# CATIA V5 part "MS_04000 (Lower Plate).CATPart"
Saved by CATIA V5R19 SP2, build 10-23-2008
Part number: MS_04000 (Lower Plate)
Bounding box of the stored display mesh (mm): x -1462.666 to 0, y -324.52 to 322.101, z 0 to 422.967
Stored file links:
  D:\EPSA\GIT\ELIZ-2022\01 - Maquette CATIA\MS_Miscellanous_Finish_Assembly\MS_A0400 (Firewall)\MS_04000 (Lower Plate).CATPart
  D:\EPSA\GIT\ELIZ-2022\01 - Maquette CATIA\MS_Miscellanous_Finish_Assembly\MS_A0400 (Firewall)\MS_A0400 (FireWall).CATProduct
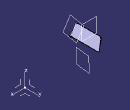
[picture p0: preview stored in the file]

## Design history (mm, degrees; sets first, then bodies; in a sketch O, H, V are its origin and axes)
AxisSystem1: origin (0, 0, 0), X (1, 0, 0), Y (0, 1, 0), Z (0, 0, 1)
Set1
  Line1: type PtPt, FirstPoint DatumPoint1, SecondPoint DatumPoint2
  Plane1: type 2Lines, Element1 Line1, Element2 Line2
  Sketch1 on Plane1, origin (-1119.4889, 0, -443.4274), H (0, 1, 0), V (-0.3683, 0, 0.9297)
    point P1 (-283.918, 931.8851)
    line L1 (-283.918, 931.8851) -> (0, 931.8851)
    line L2 (0, 655.7876) -> (-324.52, 655.7876)
    point P2 (0, 931.8851)
    point P3 (0, 655.7876)
    point P4 (-324.52, 655.7876)
    reference projected line E1 (-283.918, 931.8851) -> (283.918, 931.8851) from Line2
    reference projected point E2 (-324.52, 655.7876) from DatumPoint2
    reference projected point E3 (-283.918, 931.8851) from vertex of DatumPoint1
    reference projected point E4 (-324.52, 655.7876) from DatumPoint2
    line L3 (-283.918, 931.8851) -> (-324.52, 655.7876)
    reference intersected line E5 through (0, 0) direction (0, 1) from ZX plane of AxisSystem1
    point P7 (0, 931.8851)
    point P8 (283.918, 931.8851)
    line L4 (283.918, 931.8851) -> (0, 931.8851)
    point P9 (324.52, 655.7876)
    line L5 (283.918, 931.8851) -> (324.52, 655.7876)
    point P10 (0, 655.7876)
    line L6 (0, 655.7876) -> (324.52, 655.7876)
    horizontal: L1 H, L2 H
    coincidence: L1 E1, L2 E2, P1 E3, P4 E4, P2 E5, P3 E5, P2 P7, P3 P10
    symmetry: P2 P7 E5, P1 P8 E5, L1 L4 E5, P4 P9 E5, L3 L5 E5, P3 P10 E5, L2 L6 E5
Set2
  DatumPoint1: linked copy from another document
  DatumPoint2: linked copy from another document
  Line2: linked copy from another document
  DatumSurface1 to DatumSurface4: linked copy from another document
  Line3: linked copy from another document
Body1 (main body)
  Pad1: profile Sketch1, direction (0.9297, 0, 0.3683), length 4
  Sketch2 on end face of Pad1, origin (-1115.77, 0, -441.9543), H (0, 1, 0), V (-0.3683, 0, 0.9297)
    intersected curve E1 from face of DatumSurface1
    intersected curve E2 from face of DatumSurface2
  Pocket1: profile Sketch2, direction (-0.9297, 0, -0.3683), up to start face of Pad1
  Sketch3 on start face of Pad1, origin (-1119.4889, 0, -443.4274), H (0, -1, 0), V (-0.3683, 0, 0.9297)
    intersected curve E1 from face of DatumSurface1
    intersected curve E2 from face of DatumSurface2
  Pocket2: profile Sketch3, direction (0.9297, 0, 0.3683), up to end face of Pad1
  Sketch4 on end face of Pad1, origin (-1115.77, 0, -441.9543), H (0, 1, 0), V (-0.3683, 0, 0.9297)
    frozenspline C1
    point P1 (295.7824, 887.7626)
    point P2 (263.0227, 1006.7097)
    frozenspline C2
    point P3 (-295.7827, 887.7615)
    point P4 (-263.023, 1006.7087)
    frozenspline C3
    point P5 (263.0227, 1006.7097)
    point P6 (295.7824, 887.7626)
    frozenspline C4
    point P7 (-295.7827, 887.7615)
    point P8 (-263.023, 1006.7087)
    coincidence: P1 P6, P2 P5, P3 P7, P4 P8
  Pocket3: profile Sketch4, direction (-0.9297, 0, -0.3683), up to start face of Pad1
  Sketch5 on start face of Pad1, origin (-1119.4889, 0, -443.4274), H (0, -1, 0), V (-0.3683, 0, 0.9297)
    frozenspline C1
    point P1 (-300.2963, 872.4157)
    point P2 (-267.5366, 991.3628)
    frozenspline C2
    point P3 (300.2966, 872.4146)
    point P4 (267.5369, 991.3618)
    frozenspline C3
    point P5 (300.2966, 872.4146)
    point P6 (267.5369, 991.3618)
    frozenspline C4
    point P7 (-300.2963, 872.4157)
    point P8 (-267.5366, 991.3628)
    coincidence: P1 P7, P2 P8, P3 P5, P4 P6
  Pocket4: profile Sketch5, direction (0.9297, 0, 0.3683), up to end face of Pad1
  Sketch6 on end face of Pad1, origin (-1115.77, 0, -441.9543), H (0, 1, 0), V (-0.3683, 0, 0.9297)
    intersected line E1 (274.1166, 917.4282) -> (-274.1164, 917.4282) from face of DatumSurface3
    line L1 (-274.1164, 917.4282) -> (-274.1164, 931.8851)
    line L2 (-274.1164, 931.8851) -> (274.1166, 931.8851)
    line L3 (274.1166, 931.8851) -> (274.1166, 917.4282)
    reference projected line E2 (-283.918, 931.8851) -> (283.918, 931.8851) from Line2
    vertical: L1 V
    horizontal: L2 H
    perpendicularity: L3 L2
    coincidence: L2 E2
  Pocket5: profile Sketch6, direction (-0.9297, 0, -0.3683), up to start face of Pad1
  Sketch7 on start face of Pad1, origin (-1119.4889, 0, -443.4274), H (0, -1, 0), V (-0.3683, 0, 0.9297)
    intersected line E1 (-264.6946, 946.8851) -> (264.6946, 946.8851) from face of DatumSurface4
    point P1 (-264.6946, 946.8851)
    intersected line E2 (272.9575, 916.8851) -> (-272.9576, 916.8851) from face of DatumSurface3
    line L1 (264.6946, 946.8851) -> (272.9575, 916.8851)
    line L2 (-264.6946, 946.8851) -> (-272.9576, 916.8851)
    point P5 (-264.6946, 946.8851)
    coincidence: P5 E1, P5 P1
  Pocket6: profile Sketch7, direction (0.9297, 0, 0.3683), up to end face of Pad1
  Plane2: type Normal, Curve Line3
  Sketch8 on Plane2, origin (-1048.9767, 130.4708, 0.324), H (0.1234, 0.9924, 0), V (0.0003, 0, 1)
    circle A1 centre (154.2898, 167.552) radius 14
    point P1 (154.2898, 167.552)
    reference intersected point E1 (154.2898, 167.552) from Line3
    radius A1 = 14
    coincidence: E1 P1
  Pocket7: profile Sketch8, direction (-0.9924, 0.1234, 0.0003), up to start face of Pad1
  Plane3: type Normal, Curve Line2
  Sketch9 on Plane3, origin (0, 0, 0), H (-1, 0, 0), V (0, 0, 1)
    reference projected point E1 (1360.99, 166.273) from vertex of DatumPoint2
    circle A1 centre (1360.99, 166.273) radius 7.5
    point P1 (1360.99, 166.273)
    radius A1 = 7.5
    coincidence: E1 P1
  Pocket8: profile Sketch9, direction (0, -1, 0), up to face of Pad1 from Sketch1.L3, opposite side up to face of Pad1 from Sketch1.L5
  Sketch10 on start face of Pad1, origin (-1119.4889, 0, -443.4274), H (0, -1, 0), V (-0.3683, 0, 0.9297)
    point P4 (-311.6851, 662.1319)
    point P5 (-311.6851, 662.1319)
    line L1 (-311.6851, 662.1319) -> (311.5877, 662.1319)
    horizontal: L1 H
    coincidence: P4 P5
  Pocket9: profile Sketch10, direction (0.9297, 0, 0.3683), up to end face of Pad1
  Sketch11 on start face of Pad1, origin (-1119.4889, 0, -443.4274), H (0, -1, 0), V (-0.3683, 0, 0.9297)
  Pocket10: profile Sketch11, direction (0.9297, 0, 0.3683), up to end face of Pad1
